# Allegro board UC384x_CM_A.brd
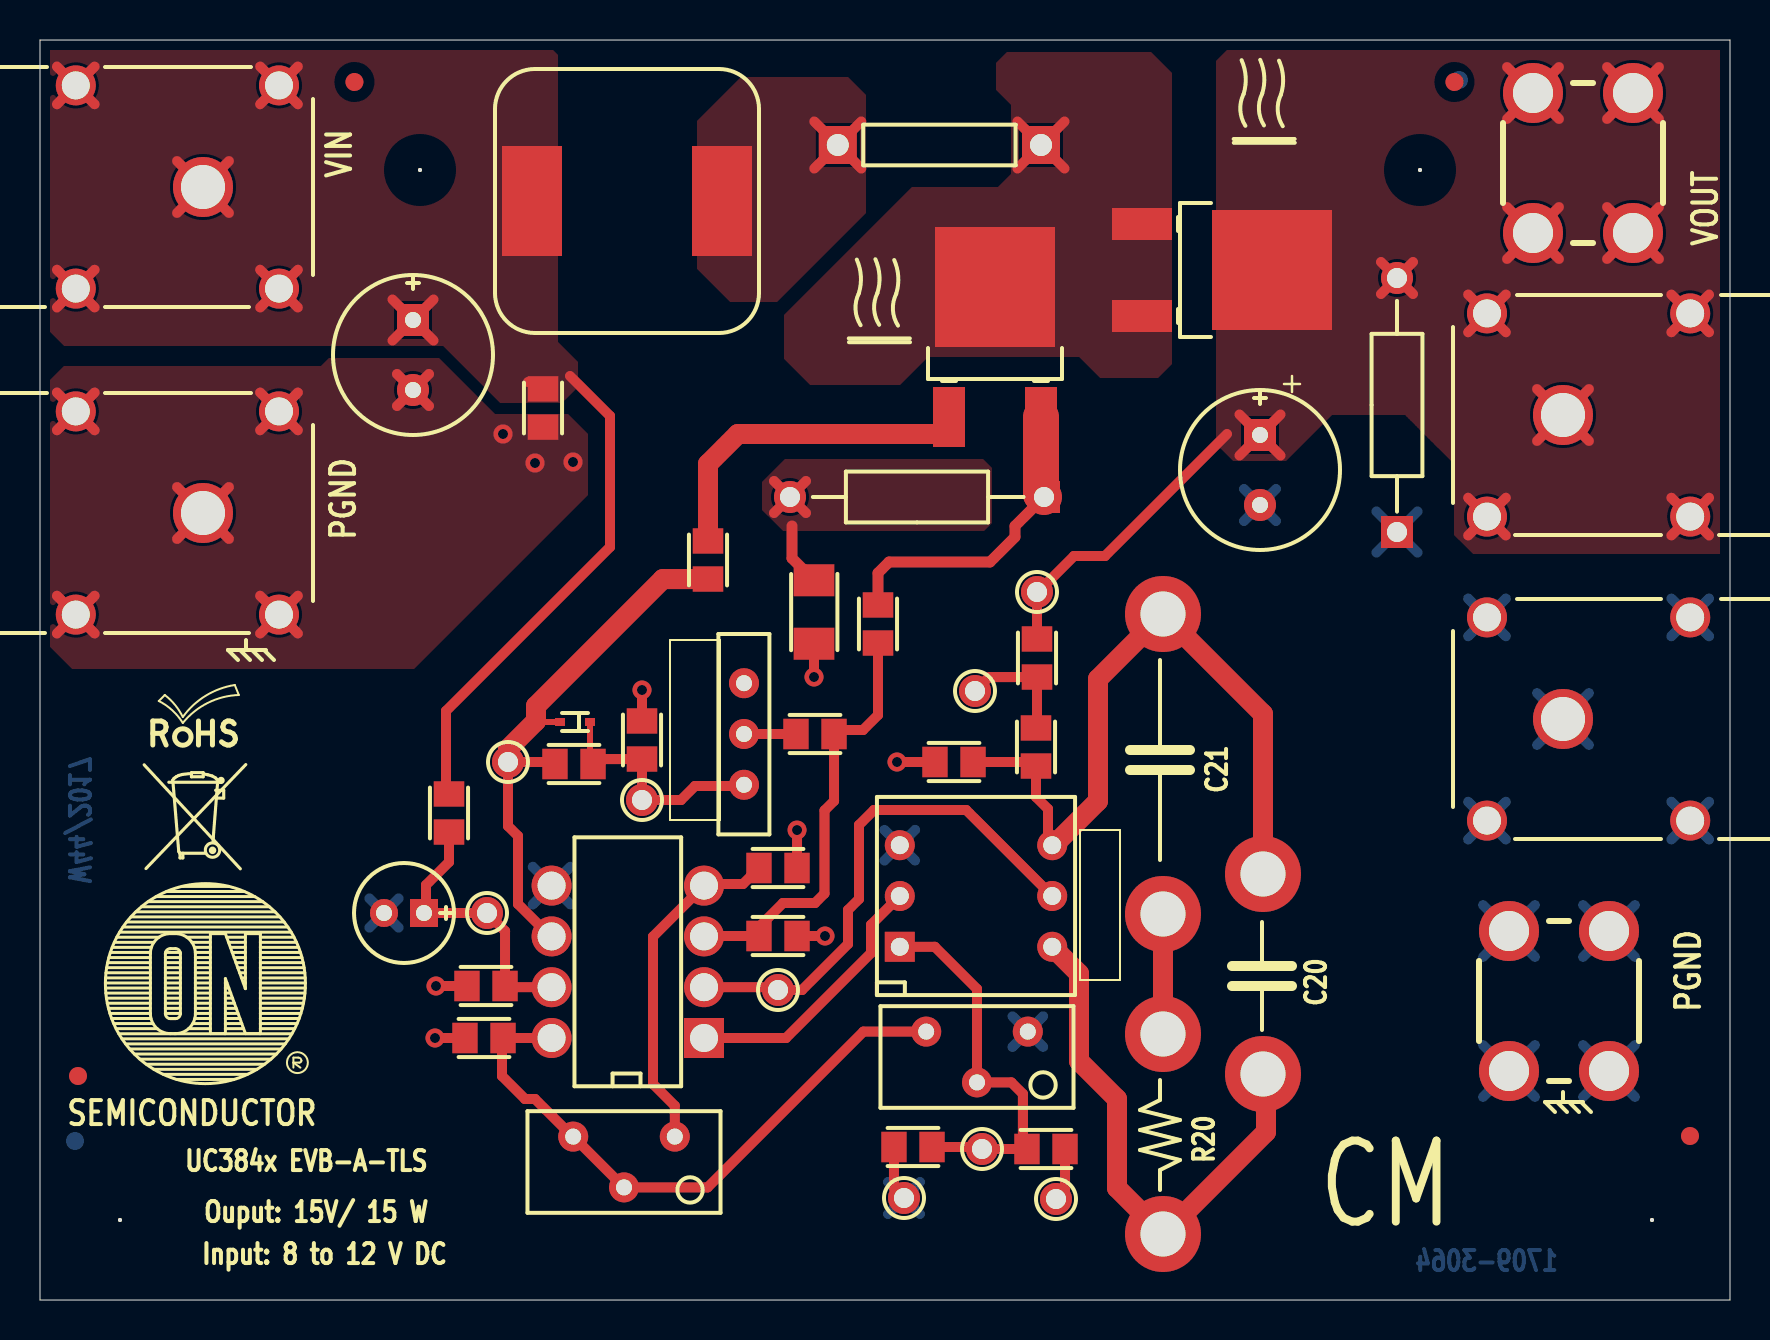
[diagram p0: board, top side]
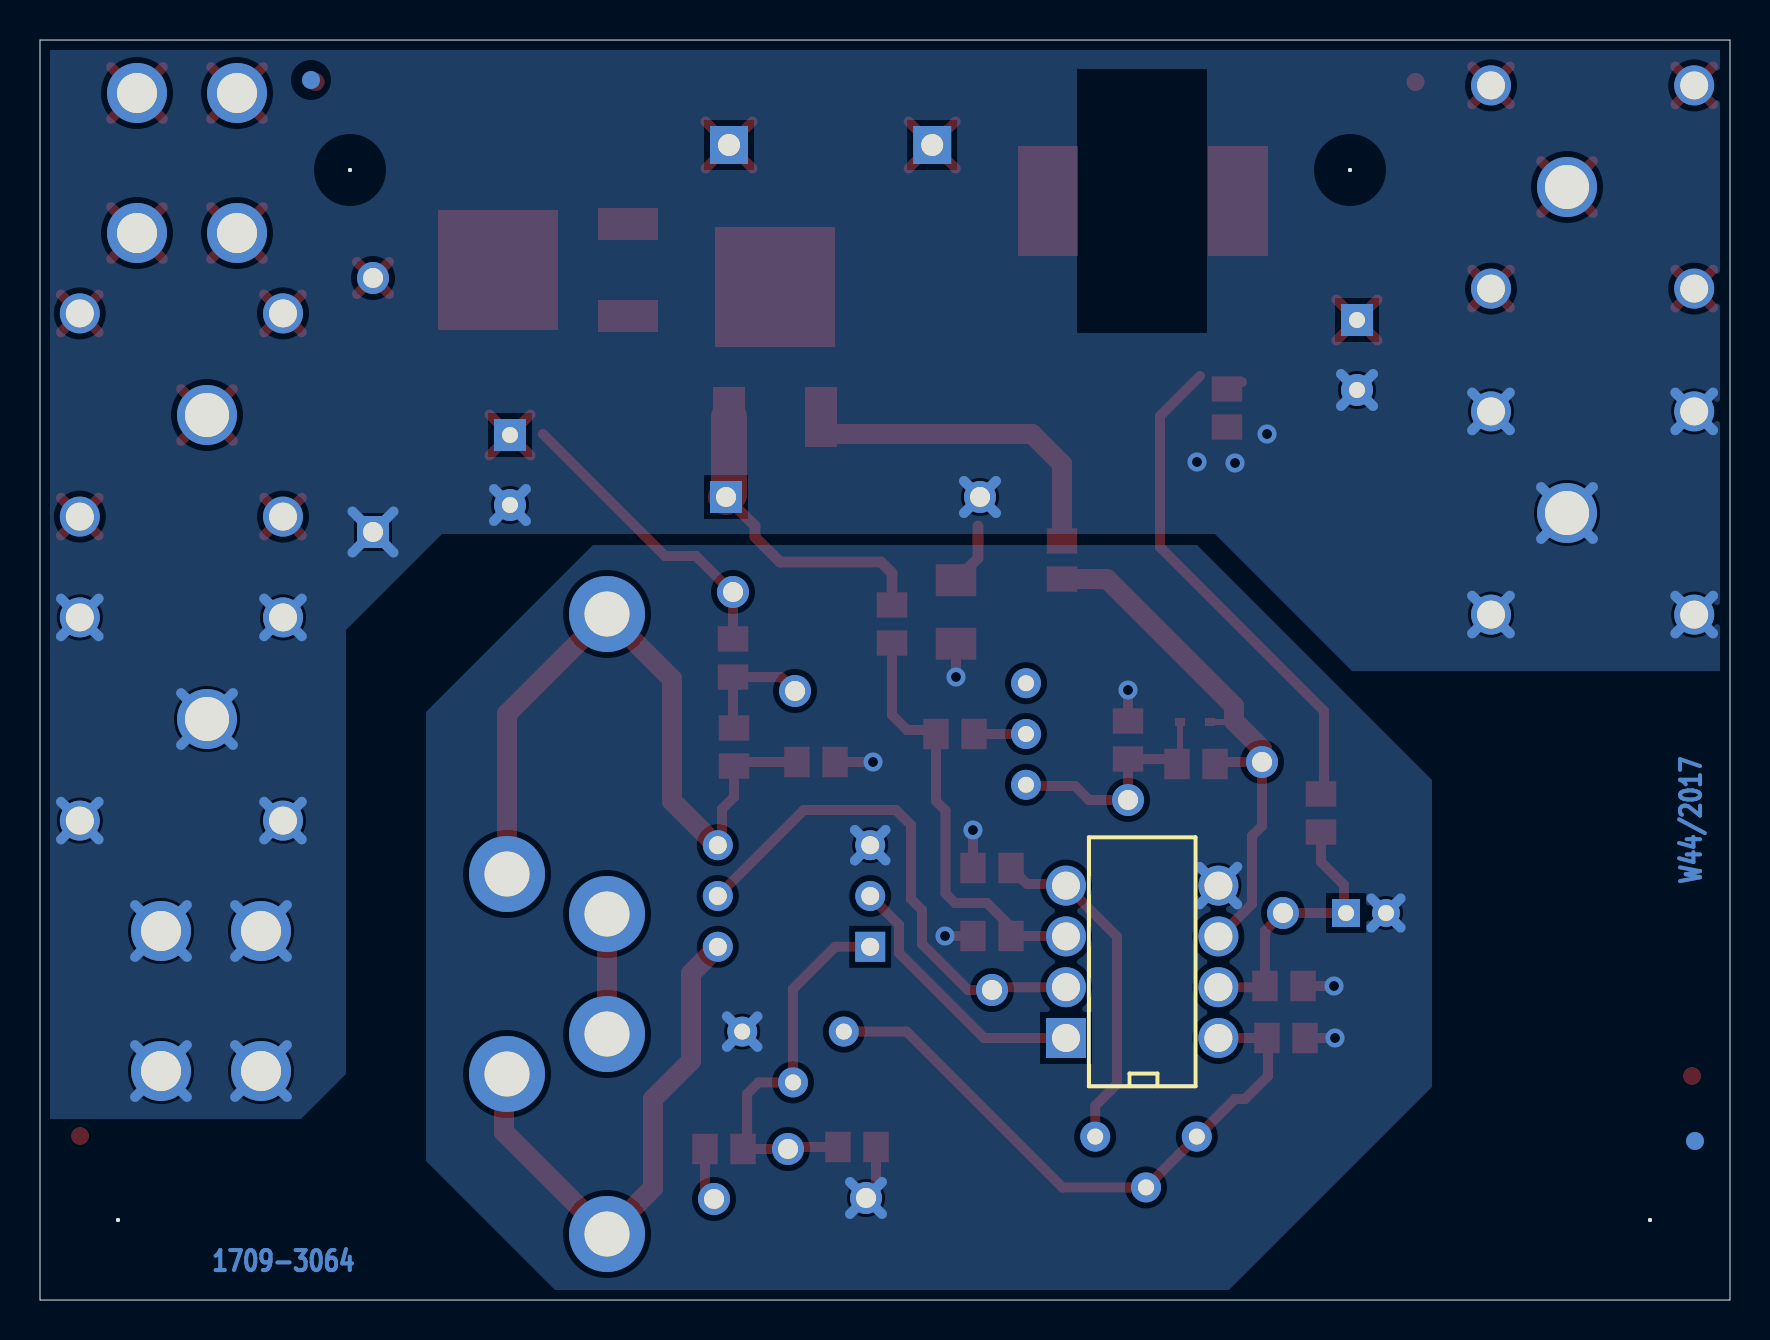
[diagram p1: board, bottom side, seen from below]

Outline 84.5 x 63 mm; copper layers: TOP, IN1, IN2, BOTTOM. Coordinates in mm from the lower left corner of the outline.
Outline path: 0,63 0,0 84.5,0 84.5,63 0,63

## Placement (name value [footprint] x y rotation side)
ACM_H  TEST POINT  [TP]  50.8 5.05 180 top
ACM_L  TEST POINT  [TP]  43.2 5.1 180 top
C1  100nF  [0805]  22.2 13.1 180 top
C1A  D  [PLOT_5380598-2]  56.15 34.3 270 top
C1B  D  [PLOT_5380598-2]  56.15 19.3 270 top
C2  2.2nF  [0805]  36.9 21.6 0 top
C2A  D  [PLOT_5380598-2]  61.15 21.3 270 top
C2B  D  [PLOT_5380598-2]  61.15 11.3 270 top
C3  2.2uF  [CAPA_CH_D5_H11_P2]  18.2 19.35 180 top
C4  220uF  [CAPA_CH_D8_H12_P3V5]  61 41.5 270 top
C5  220uF  [CAPA_CH_D8_H12_P3V5]  18.65 47.25 270 top
C6  1uF  [0805]  25.15 44.6 270 top
C7  100nF  [0805]  22.3 15.7 180 top
C8  100nF  [0805]  43.65 7.65 180 top
C9  2.2uF  [0805]  50.3 7.55 180 top
C10  220pF  [0805]  36.9 18.2 0 top
C11  470pF  [0805]  30.1 28 90 top
CB1  target_cms  [MIRE_LOW]  1.75 7.95 180 bottom
CB2  target_cms  [MIRE_LOW]  70.95 61 180 bottom
CB3  target_cms  [MIRE_LOW]  1.9 11.2 0 top
CB4  target_cms  [MIRE_LOW]  70.72 60.9 0 top
CB5  target_cms  [MIRE_LOW]  82.5 8.2 0 top
CB6  target_cms  [MIRE_LOW]  15.72 60.9 0 top
COMP  TEST POINT  [TP]  36.9 15.5 180 top
D1  1N4148  [SOD523]  26.75 28.9 180 top
D3  MBRD1045T4G  [DPAK_TO252]  60 51.5 270 top
DRV  TEST POINT  [TP]  23.4 26.9 180 top
J1A  SLB4-I/90_R  [BANANE_4MM_SLB4]  8.15 55.65 180 top
J1B  SLB4-I/90_B  [BANANE_4MM_SLB4]  8.15 39.35 180 top
J1C  SLB4-I/90_R  [BANANE_4MM_SLB4]  76.15 44.25 0 top
J1D  SLB4-I/90_B  [BANANE_4MM_SLB4]  76.15 29.05 0 top
J2A  Screw_terminal  [PC_7701]  77.15 56.85 0 top
J2B  Screw_terminal  [PC_7701]  75.95 14.95 0 top
L1  180uH  [SELF_MSS1210]  29.35 54.95 90 top
NOREF  -  []  84.5 0 90 top
NOREF#2  -  []  -181.6 -74.35 0 top
NOREF#3  -  [unnamed#2]  19 56.5 0 top
NOREF#4  -  []  -114.15 -47.45 0 top
NOREF#5  -  [unnamed#2]  80.6 4 0 top
NOREF#6  -  []  80.6 4 0 top
NOREF#7  -  []  0 63 0 top
NOREF#8  -  [unnamed#2]  4 4 0 top
NOREF#9  -  []  84.5 0 90 top
NOREF#10  -  [unnamed#2]  69 56.5 0 top
NOREF#11  -  []  283.55 -63.75 180 bottom
P1  10K  [POTAR_12T_3266W]  46.85 12.15 180 top
P2  20K  [POTAR_12T_3266W]  29.2 6.9 180 top
Q1  NTD5865NLT4G  [DPAK_TO252]  47.75 49.05 0 top
R1  11K  [0805]  49.8 27.65 90 top
R2  650R  [0805]  41.9 33.8 270 top
R2A  D  [PLOT_5380598-2]  56.15 13.3 270 top
R2B  D  [PLOT_5380598-2]  56.15 3.3 270 top
R4  22K  [0805]  26.7 26.8 0 top
R5  10R  [0805]  20.45 24.35 90 top
R6  100K  [0805]  38.75 28.3 180 top
R7  2.2K  [0805]  45.7 26.9 0 top
R8  10R  [0805]  49.85 32.1 90 top
R9  10R  [0805]  33.4 37 90 top
R10  0R  [1206]  38.7 34.4 90 top
R11  1K / 0.5W  [RC21U]  67.85 44.75 90 top
R12  0.4R  [RC21U]  43.85 40.15 180 top
RAMP  TEST POINT  [TP]  30.1 25 180 top
S1  Strap  [JUMPER400H]  50.05 57.75 180 top
SW1  DPDT  [SW_76SD01ST]  46.8 20.2 0 top
SW2  DPDT  [SWITCH-1K2]  35.2 28.3 90 top
U1  UC3845B  [DIP8_SUP]  33.2 13.1 180 top
VA  TEST POINT  [TP]  49.85 35.4 0 top
VB  TEST POINT  [TP]  46.75 30.45 0 top
VCC  TEST POINT  [TP]  22.35 19.35 180 top
VSET  TEST POINT  [TP]  47.1 7.55 180 top

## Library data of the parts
ACM_H ACM_L COMP DRV RAMP S1 VA VB VCC VSET = TEST POINT_0
C1-C3 C6-C11 = C
C1A C1B C2A C2B R2A R2B = T POINT R_0
C4 C5 = C_elect_0
CB1-CB6 = target_cms
D1 = D1N4148
D3 = dual_diodeAAK
J1A J1B J1C J1D = HEADER 1_0
J2A J2B = 4 HEADER_0
L1 = L
P1 P2 = RESISTOR VAR
Q1 = NMOS_3
R1 R2 R4-R9 R11 R12 = R
R10 = R: alternate symbols: (RES_1W_D5XL12_jp)
SW1 = SW DPDT/SM_0
SW2 = SW SPST
U1 = UC3845B

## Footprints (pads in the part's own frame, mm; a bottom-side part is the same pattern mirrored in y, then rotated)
0805
  rect 1.27x1.524 smd: 1(-0.953,0) 2(0.953,0)
1206
  rect 1.6x2.03 smd: 1(-1.587,0) 2(1.587,0)
BANANE_4MM_SLB4
  round 3 hole 2.2: 1(0,0)
  round 2 hole 1.4: 2(-3.8,5.08) 3(-3.8,-5.08) 4(6.36,5.08) 5(6.36,-5.08)
CAPA_CH_D5_H11_P2
  rect 1.4x1.4 hole 0.8: 1(-1,0)
  round 1.4 hole 0.8: 2(1,0)
CAPA_CH_D8_H12_P3V5
  rect 1.6x1.6 hole 0.8: 1(-1.75,0)
  round 1.6 hole 0.8: 2(1.75,0)
DIP8_SUP
  rect 2x2 hole 1.4: 1(0,0)
  round 2 hole 1.4: 2(0,-2.54) 3(0,-5.08) 4(0,-7.62) 5(7.62,-7.62) 6(7.62,-5.08) 7(7.62,-2.54) 8(7.62,0)
DPAK_TO252
  rect 1.6x3 smd: 1(-2.3,-4.9) 3(2.3,-4.9)
  rect 6x6 smd: 2(0,1.6)
JUMPER400H
  rect 1.9x1.9 hole 1.1: 1(0,0) 2(10.16,0)
MIRE_LOW
  round 0.9 smd: 1(0,0)
PC_7701
  round 3 hole 2: 1(-2.5,-3.5) 2(2.5,-3.5) 3(2.5,3.5) 4(-2.5,3.5)
PLOT_5380598-2
  round 3.8 hole 2.25: 1(0,0)
POTAR_12T_3266W
  round 1.5 hole 0.8: 1(-2.54,-1.27) 2(0,1.27) 3(2.54,-1.27)
RC21U
  rect 1.6x1.6 hole 1: 1(-6.35,0)
  round 1.6 hole 1: 2(6.35,0)
SELF_MSS1210
  rect 5.5x3 smd: 1(0,4.75) 2(0,-4.75)
SOD523
  rect 0.5x0.4 smd: 1(-0.75,0) 2(0.75,0)
SW_76SD01ST
  rect 1.5x1.5 hole 0.9: 1(-3.81,-2.54)
  round 1.5 hole 0.9: 2(-3.81,2.54) 11(3.81,-2.54) 22(3.81,2.54) C1(-3.81,0) C2(3.81,0)
SWITCH-1K2
  round 1.5 hole 0.8: 1(-2.54,0) 2(0,0) 3(2.54,0)
TP
  round 1.6 hole 1: 1(0,0)
unnamed#2
  round 0.2 hole 3 unplated: (0,0)

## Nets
GND_EARTH: ACM_L.1 C1.2 C2.2 C3.2 C7.2 C8.2 C10.2 C11.2 P1.1(A) R7.1 R10.1 SW1.2(NO2) U1.5(GND)
GND_SIGNAL: C4.2(-) C5.2(-) C6.2 J1B.1 J1B.2 J1B.3 J1B.4 J1B.5 J1D.1 J1D.2 J1D.3 J1D.4 J1D.5 J2B.1 J2B.2 J2B.3 J2B.4 R10.2 R11.1 R12.2
VCC: C3.1 C7.1 R5.1 U1.7(VCC) VCC.1
VIN: C5.1(+) C6.1 J1A.1 J1A.2 J1A.3 J1A.4 J1A.5 L1.1 R5.2
DRV: D1.2 DRV.1 R4.1 R9.1 U1.6(DRV)
REF: C1.1 P1.3(B) P2.2(WIPER) P2.3(B) U1.8(REF)
VOUT: C4.1(+) D3.2(C) J1C.1 J1C.2 J1C.3 J1C.4 J1C.5 J2A.1 J2A.2 J2A.3 J2A.4 R8.2 R11.2 VA.1
N12290274: L1.2 S1.2
N12290314: D3.1(A1) D3.3(A2) Q1.2(D) S1.1
N12290349: Q1.3(S) R2.1 R12.1
N12292005: Q1.1(G) R9.2
N12295463: C2.1 P2.1(A) U1.4(RT/CT)
N12295845: C10.1 R2.2 R6.1 U1.3(IS)
N12296104: COMP.1 SW1.C2(COMMON2) U1.2(FB)
N12296108: SW1.C1(COMMON1) U1.1(EA)
N12296437: C11.1 D1.1 R4.2 RAMP.1 SW2.1
N12297349: R1.2 R8.1 VB.1
N12298127: C1A.1(TP) C2A.1(TP) R1.1 R7.2 SW1.22(NC2)
N12298463: C8.1 C9.2 P1.2(WIPER) SW1.1(NO1) VSET.1
N12299817: C1B.1(TP) R2A.1(TP)
N12299821: C2B.1(TP) R2B.1(TP) SW1.11(NC1)
N12301916: ACM_H.1 C9.1
N122961380: R6.2 SW2.2

Pads without a net: CB1 1; CB2 1; CB3 1; CB4 1; CB5 1; CB6 1; SW2 3

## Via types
v1: diameter 0.95, hole 0.5, TOP to BOTTOM, 10 vias

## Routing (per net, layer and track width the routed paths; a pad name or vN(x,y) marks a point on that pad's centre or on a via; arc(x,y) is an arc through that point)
GND_EARTH: length 36.8
  TOP w0.5: R10.1 v1(38.7,31.15) ; C10.2 v1(39.25,18.2) ; C2.2 v1(37.85,23.5) ; C7.2 v1(19.8,15.7) ; ACM_L.1 42.7,5.6 C8.2 ; R7.1 v1(42.85,26.9) ; C1.2 v1(19.75,13.1) ; C11.2 v1(30.1,30.5)
  BOTTOM w0.5: P1.1 50.15,14.18 ; P1.1 48.63,12.66 ; P1.1 50.15,12.66 ; P1.1 48.63,14.18 ; C3.2 17.93,18.62 ; C3.2 16.47,20.08 ; C3.2 16.47,18.62 ; C3.2 17.93,20.08 ; 24.64,19.78 U1.5 ; U1.5 26.52,19.78 ; U1.5 24.64,21.66 ; U1.5 26.52,21.66 ; ACM_L.1 44,5.9 ; ACM_L.1 42.4,4.3 ; ACM_L.1 42.4,5.9 ; ACM_L.1 44,4.3 ; SW1.2 43.75,21.98 ; SW1.2 42.23,21.98 ; SW1.2 43.75,23.5 ; SW1.2 42.23,23.5
GND_SIGNAL: length 146.8
  TOP w0.5: J1B.4 2.73,35.21 ; J1B.4 2.73,33.33 ; J1B.4 0.85,33.33 ; J1B.4 0.85,35.21 ; J1B.2 12.89,33.33 ; J1B.2 12.89,35.21 ; J1B.2 11.01,35.21 ; J1B.2 11.01,33.33 ; J1B.1 9.44,38.06 ; J1B.1 6.86,40.64 ; J1B.1 9.44,40.64 ; J1B.1 6.86,38.06 ; J1B.3 12.89,45.37 ; J1B.3 11.01,43.49 ; J1B.3 12.89,43.49 ; J1B.3 11.01,45.37 ; 17.85,46.3 C5.2 ; C5.2 17.85,44.7 ; C5.2 19.45,46.3 ; C5.2 19.45,44.7 ; 36.7,39.35 R12.2 ; R12.2 38.3,40.95 ; R12.2 36.7,40.95 ; R12.2 38.3,39.35 ; 0.85,43.49 J1B.5 ; J1B.5 0.85,45.37 ; J1B.5 2.73,43.49 ; J1B.5 2.73,45.37
  TOP w0.54: R10.2 37.6,37.09 37.6,38.7
  BOTTOM w0.5: J2B.4 74.74,17.16 ; J2B.4 74.74,19.74 ; J2B.4 72.16,17.16 ; J2B.4 72.16,19.74 ; J1D.4 83.45,35.07 ; J1D.4 81.57,33.19 ; J1D.4 83.45,33.19 ; J1D.4 81.57,35.07 ; 60.2,38.95 C4.2 ; C4.2 61.8,40.55 ; C4.2 61.8,38.95 ; C4.2 60.2,40.55 ; J1B.5 2.73,43.49 ; J1B.5 0.85,43.49 ; J1B.5 0.85,45.37 ; J1B.5 2.73,45.37 ; R12.2 38.3,39.35 ; R12.2 36.7,39.35 ; R12.2 38.3,40.95 ; R12.2 36.7,40.95 ; 66.82,39.43 R11.1 ; R11.1 68.88,39.43 ; R11.1 66.82,37.37 ; R11.1 68.88,37.37 ; 71.41,23.03 J1D.3 ; J1D.3 71.41,24.91 ; J1D.3 73.29,23.03 ; J1D.3 73.29,24.91 ; 17.85,44.7 C5.2 ; C5.2 19.45,44.7 ; C5.2 17.85,46.3 ; C5.2 19.45,46.3 ; 72.16,12.74 J2B.1 ; J2B.1 72.16,10.16 ; J2B.1 74.74,10.16 ; J2B.1 74.74,12.74 ; J2B.3 79.74,17.16 ; J2B.3 79.74,19.74 ; J2B.3 77.16,17.16 ; J2B.3 77.16,19.74 ; J1D.5 83.45,23.03 ; J1D.5 81.57,24.91 ; J1D.5 81.57,23.03 ; J1D.5 83.45,24.91 ; J2B.2 79.74,12.74 ; J2B.2 77.16,10.16 ; J2B.2 79.74,10.16 ; J2B.2 77.16,12.74 ; 11.01,45.37 J1B.3 ; J1B.3 12.89,45.37 ; J1B.3 12.89,43.49 ; J1B.3 11.01,43.49 ; J1D.2 73.29,33.19 ; J1D.2 71.41,35.07 ; J1D.2 73.29,35.07 ; J1D.2 71.41,33.19 ; J1D.1 77.44,27.76 ; J1D.1 77.44,30.34 ; J1D.1 74.86,27.76 ; J1D.1 74.86,30.34 ; J1B.4 2.73,33.33 ; J1B.4 0.85,35.21 ; J1B.4 2.73,35.21 ; J1B.4 0.85,33.33 ; 6.86,40.64 J1B.1 ; J1B.1 9.44,40.64 ; J1B.1 6.86,38.06 ; J1B.1 9.44,38.06 ; 11.01,35.21 J1B.2 ; J1B.2 12.89,33.33 ; J1B.2 12.89,35.21 ; J1B.2 11.01,33.33
  vias: v1(23.15,43.3) v1(24.75,41.85) v1(26.65,41.9)
VCC: length 14.1
  TOP w0.5: R5.1 20.45,21.9 19.3,20.75 19.3,19.45 C3.1 VCC.1 23.25,18.45 C7.1 23.31,15.64 U1.7
VIN: length 60.8
  TOP w0.5: 26.5,46.2 28.5,44.2 28.5,37.65 20.3,29.45 20.3,25.45 R5.2 ; 6.86,56.94 J1A.1 ; J1A.1 9.44,54.36 ; J1A.1 9.44,56.94 ; J1A.1 6.86,54.36 ; 11.01,61.67 J1A.3 ; J1A.3 12.89,61.67 ; J1A.3 11.01,59.79 ; J1A.3 12.89,59.79 ; J1A.5 2.73,61.67 ; J1A.5 0.85,61.67 ; J1A.5 0.85,59.79 ; J1A.5 2.73,59.79 ; J1A.4 2.73,51.51 ; J1A.4 0.85,49.63 ; J1A.4 2.73,49.63 ; J1A.4 0.85,51.51 ; 25.55,45.9 24.4,45.9 ; 17.62,50.03 C5.1 ; C5.1 19.68,47.97 ; C5.1 19.68,50.03 ; C5.1 17.62,47.97 ; J1A.2 12.89,49.63 ; J1A.2 11.01,49.63 ; J1A.2 12.89,51.51 ; J1A.2 11.01,51.51
DRV: length 27.9
  TOP w0.3: 24.8,28.95 24.85,28.9 D1.2
  TOP w0.5: R4.1 25.65,26.9 DRV.1 23.4,23.7 23.9,23.2 23.9,19.8 25.52,18.18 U1.6
  TOP w1: R9.1 31.15,36.05 24.8,29.7 24.8,28.95 23.4,27.55 DRV.1
REF: length 31.1
  TOP w0.5: P1.3 41.17,13.42 33.38,5.63 P2.2 P2.3 26.63,8.17 24.75,10.05 24.25,10.05 23.1,11.2 23.1,13.05 C1.1 U1.8
VOUT: length 83.4
  TOP w0.5: J1C.5 83.45,40.11 ; J1C.5 81.57,38.23 ; J1C.5 81.57,40.11 ; J1C.5 83.45,38.23 ; J2A.1 75.94,52.06 ; J2A.1 73.36,54.64 ; J2A.1 73.36,52.06 ; J2A.1 75.94,54.64 ; J1C.2 73.29,48.39 ; J1C.2 71.41,48.39 ; J1C.2 71.41,50.27 ; J1C.2 73.29,50.27 ; 81.57,48.39 J1C.4 ; J1C.4 83.45,50.27 ; J1C.4 81.57,50.27 ; J1C.4 83.45,48.39 ; J2A.3 80.94,59.06 ; J2A.3 80.94,61.64 ; J2A.3 78.36,61.64 ; J2A.3 78.36,59.06 ; 59.97,42.22 C4.1 ; C4.1 59.97,44.28 ; C4.1 62.03,42.22 ; C4.1 62.03,44.28 ; 71.41,38.23 J1C.3 ; J1C.3 71.41,40.11 ; J1C.3 73.29,38.23 ; J1C.3 73.29,40.11 ; J2A.4 75.94,59.06 ; J2A.4 73.36,59.06 ; J2A.4 73.36,61.64 ; J2A.4 75.94,61.64 ; 74.86,45.54 J1C.1 ; J1C.1 77.44,42.96 ; J1C.1 74.86,42.96 ; J1C.1 77.44,45.54 ; 67.05,50.3 R11.2 ; R11.2 68.65,51.9 ; R11.2 67.05,51.9 ; R11.2 68.65,50.3 ; 78.36,54.64 J2A.2 ; J2A.2 80.94,52.06 ; J2A.2 80.94,54.64 ; J2A.2 78.36,52.06 ; 59.35,43.3 53.25,37.2 51.7,37.2 49.9,35.4 VA.1 R8.2
N12290274: length 6.6
  TOP w0.5: S1.2 41.07,58.93 ; S1.2 38.71,58.93 ; S1.2 38.71,56.57 ; S1.2 41.07,56.57
N12290314: length 6.6
  TOP w0.5: 48.87,58.93 S1.1 ; S1.1 48.87,56.57 ; S1.1 51.23,58.93 ; S1.1 51.23,56.57
N12290349: length 15.9
  TOP w0.54: R12.1 48.75,38.7 48.75,38.15 47.5,36.9 42.45,36.9 41.9,36.35 R2.1
  TOP w1.8: R12.1 50.05,40.3 Q1.3
N12292005: length 17.1
  TOP w1: R9.2 33.4,41.8 34.9,43.3 45.05,43.3 45.45,43.7 Q1.1
N12295463: length 17.2
  TOP w0.5: P2.1 31.74,9.71 30.65,10.8 30.65,18.17 U1.4 33.28,20.8 35.15,20.8 C2.1
N12295845: length 21.6
  TOP w0.5: R2.2 41.9,29.25 41.15,28.5 39.9,28.5 R6.1 39.7,24.95 39.23,24.48 39.23,20.33 38.75,19.85 37.15,19.85 35.7,18.4 35.7,18.2 ; 35.7,18.2 C10.1 ; 35.7,18.2 33.22,18.2 U1.3
N12296104: length 26.1
  TOP w0.5: SW1.C2 46.31,24.5 41.7,24.5 40.95,23.75 40.95,20.05 40.4,19.5 40.4,17.8 38.1,15.5 COMP.1 36.76,15.64 U1.2
N12296108: length 13.6
  TOP w0.5: SW1.C1 41.55,18.76 41.55,17.35 37.3,13.1 U1.1
N12296437: length 12.2
  TOP w0.3: R4.2 27.5,26.95 D1.1
  TOP w0.5: SW2.1 35.14,25.7 32.75,25.7 32.05,25 RAMP.1 C11.1 27.9,27.05 R4.2
N12297349: length 6
  TOP w0.5: R1.2 49.85,28.65 R8.1 47.45,31.15 VB.1
N12298127: length 36.5
  TOP w0.5: SW1.22 50.4,22.95 50.4,24.55 49.8,25.15 R1.1 49.6,26.9 R7.2
  TOP w1: SW1.22 50.69,22.74 52.9,24.95 52.9,31.05 C1A.1 61.15,29.3 C2A.1
N12298463: length 19.6
  TOP w0.5: 49.39,7.59 C9.2 ; C9.2 49.15,7.75 49.15,10.3 48.57,10.88 P1.2 46.85,15.55 44.74,17.66 SW1.1 ; C9.2 VSET.1 47,7.65 C8.1
N12299817: length 6
  TOP w1: C1B.1 R2A.1
N12299821: length 26.9
  TOP w1: C2B.1 61.3,11.15 61.3,8.4 56.2,3.3 R2B.1 53.85,5.6 53.85,10.05 51.95,11.95 51.95,16.32 SW1.11
N12301916: length 2.7
  TOP w0.5: C9.1 51.25,5.5 ACM_H.1
N122961380: length 2.6
  TOP w0.5: R6.2 SW2.2

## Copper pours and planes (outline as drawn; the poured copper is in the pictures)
GND_EARTH on BOTTOM: 25.05,0.5 14.9,10.65 14.9,26 26.65,37.75 56.85,37.75 65.2,29.4 65.2,6.95 58.75,0.5
GND_SIGNAL on TOP: 1.6,31.55 0.5,32.65 0.5,46 1.2,46.7 14.05,46.7 14.45,47.1 19.95,47.1 22.75,44.3 26.4,44.3 27.4,43.3 27.4,40.25 18.7,31.55
GND_SIGNAL on TOP: 37.15,38.45 47.2,38.45 47.6,38.85 47.6,41.6 47.15,42.05 37.25,42.05 36.1,40.9 36.1,39.5
GND_SIGNAL on BOTTOM: 71.45,9.05 69.2,11.3 69.2,33.5 64.4,38.3 25.75,38.3 18.9,31.45 0.5,31.45 0.5,62.5 84,62.5 84,9.05
VIN on TOP: 23,44.85 20.15,47.7 1.2,47.7 0.5,48.4 0.5,62.5 25.65,62.5 25.9,62.25 25.9,47.9 26.9,46.9 26.9,45.65 26.1,44.85
Net_27 on IN2: 0,0 0,53 83.5,53 83.5,0
VOUT on TOP: 71.65,37.3 70.7,38.25 70.7,41.8 68.25,44.25 64.6,44.25 62.3,41.95 59.65,41.95 58.8,42.8 58.8,61.95 59.35,62.5 84,62.5 84,37.3
N12290274 on TOP: 41.3,54.35 41.3,60.25 40.4,61.15 35.05,61.15 32.85,58.95 32.85,51.55 34.5,49.9 36.85,49.9
N12290314 on TOP: 48.55,59.75 48.55,56.3 47.9,55.65 43.6,55.65 37.2,49.25 37.2,47.05 38.5,45.75 43,45.75 44.4,47.15 51.95,47.15 53,46.1 55.9,46.1 56.6,46.8 56.6,61.35 55.55,62.4 48.35,62.4 47.8,61.85 47.8,60.5

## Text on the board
BOTTOM: BOT 1/1 | 1709-3064 | W44/2017
Ref Des/Silkscreen Bottom: SILK_BOT
User.Comments: VE_BOT | VE_TOP
TOP: TOP 2/2
Ref Des/Silkscreen Top: UC384x EVB-A-TLS | Input: 8 to 12 V DC | Ouput: 15V/ 15 W | R20 | C21 | C20 | SEMICONDUCTOR | SILK_TOP | VIN | PGND | VOUT | CM
IN1: IN1 3/4
IN2: IN2 2/4
DIMENSION: 1.0
BODY_CENTER: 1.0
User.5: CHEMICAL NiAu | 35um(1oz)at START | THICKNESS | MATERIAL | STACKUP | FINISH | SILKSCREEN | MINIMAL GAP | MINIMAL SLIVER | BOARD THICKNESS | SOLDER MASK | COPPER THICKNESS | MARKED ON BOTTOM SOLDERMASK | ALL BOARD ELECTRICALLY TESTED | MANUFACTURE 'S LOGO & DATECODE | COMPLIANT RoHS DIRECTIVE 2011/65/UE | DF /2LAYERS | WHITE TOP | FR4 IMPROVED (low CTE) | 210um /8.0mils | GREEN TOP & BOT | 1.6mm /63mils | 1.0 | CM | SPEC:
User.6: DEMO UC384x 1709-3064   W44/2017
User.7: FIGURE | SIZE | 0.5 | 0.8 | 0.9 | 1.0 | 1.1 | 1.4 | 2.0 | 2.2 | 2.25 | 3.0 | DRILL CHART: TOP to BOTTOM | ALL UNITS ARE IN MILLIMETERS | TOLERANCE | +0.0/-0.0 | +0.05/-0.05 | PLATED | NON-PLATED | QTY | 10 | 15 | 6 | 13 | 2 | 24 | 8 | 4
